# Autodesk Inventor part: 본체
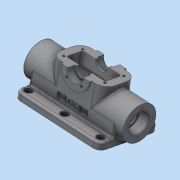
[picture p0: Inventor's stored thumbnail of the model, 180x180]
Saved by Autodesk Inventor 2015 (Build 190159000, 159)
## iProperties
Created: 2024-06
Part Number: 본체
Material: 알루미늄 6061
Document SubType Name: Modeling
Designer: Administrator
Density: 2.7 g/cm^3
Appearance: 기본값
Mass: 551.049 g
Surface Area: 614.928 cm^2
Volume: 204.092 cm^3
Author: Administrator
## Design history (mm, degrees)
sketch "스케치10"
  geometry: L1 (24, -29.5)-(-24, -29.5); L2 (-24, -29.5)-(-24, 29.5); L3 (-24, 29.5)-(24, 29.5); L4 (24, 29.5)-(24, -29.5); L5 (24, -29.5)-(-24, 29.5); L6 (-24, -29.5)-(24, 29.5); 1 further point
  constraints: 12 end point, 2 midpoint, 2 parallel, 1 horizontal, 1 perpendicular
  dimensions: "d38" = 48 distance of L2.end L3.end; "d39" = 59 distance of L3.end L1.start
extrude "돌출7" new body sketch "스케치10" stored distance "d40" = 84; taper "d41" = 0 deg
fillet "모깎기1" dims "d42" = 15
sketch "스케치11"
  geometry: L1 (18, 0)-(0, 0) reference; L2 (33, 15)-(33, 69) reference; L3 (0, 84)-(18, 84) reference; L4 (-15, 69)-(-15, 15) reference; L5 (53, -24)-(-35, -24); L6 (-35, -24)-(-35, 108); L7 (-35, 108)-(53, 108); L8 (53, 108)-(53, -24); L9 (53, -24)-(-35, 108); L10 (-35, -24)-(53, 108); A1 r 15 centre (0, 15) between (-15, 15) and (0, 0) reference; A2 r 15 centre (18, 15) between (18, 0) and (33, 15) reference; A3 r 15 centre (18, 69) between (33, 69) and (18, 84) reference; A4 r 15 centre (0, 69) between (0, 84) and (-15, 69) reference; 1 further point
  constraints: 12 end point, 2 midpoint, 2 parallel, 1 horizontal, 1 perpendicular
  dimensions: "d43" = 88 distance of L5.start L5.end; "d44" = 132 distance of L5.end L6.end
extrude "돌출8" join sketch "스케치11" distance "d45" = 10; taper "d46" = 0 deg
sketch "스케치12"
  geometry: L1 (44, -29.5)-(-44, -29.5) reference; C1 r 24 at (0, -1.5); 1 further point
  constraints: 1 centre point, 1 vertical alignment
  dimensions: "d47" = 48 diameter of C1; "d48" = 28 distance from line of L1 C1.centre
extrude "돌출9" join sketch "스케치12" stored distance "d49" = 154; taper "d50" = 0 deg
sketch "스케치13"
  geometry: L1 (24, -1.5)-(24, -19.5) reference; L2 (-24, -19.5)-(-24, -1.5) reference; L3 (-15.875, -19.5)-(-24, -19.5) reference; L4 (24, -19.5)-(15.875, -19.5) reference; L5 (-24, -1.5)-(-24, -19.5); L6 (15.875, -19.5)-(24, -19.5); L7 (24, -1.5)-(24, -19.5); L8 (-15.875, -19.5)-(-24, -19.5); 1 further point
  constraints: 8 end point, 2 collinear, 2 perpendicular, 2 other
extrude "돌출10" join sketch "스케치13" stored distance "d51" = 132; taper "d52" = 0 deg
sketch "스케치14"
  geometry: L1 (22.5, 77)-(-25.5, 77) reference; L2 (-25.5, -77)-(22.5, -77) reference; L3 (-1.5, 77)-(-1.5, -77); L4 (-29.5, -66)-(-29.5, 66) reference; L5 (12.5, 77)-(12.5, 62); L6 (12.5, 62)-(9.5, 62); L7 (9.5, 62)-(9.5, 60); L8 (9.5, 60)-(16.5, 60); L9 (16.5, 60)-(16.5, -60); L10 (16.5, -60)-(9.5, -60); L11 (9.5, -60)-(9.5, -62); L12 (9.5, -62)-(12.5, -62); L13 (12.5, -62)-(12.5, -77); L14 (22.5, -77)-(22.5, -42) reference; 1 further point
  constraints: 20 end point, 8 perpendicular, 5 point on line, 2 midpoint, 1 collinear, 1 vertical
  dimensions: "d53" = 28 distance between parallel lines of L4 L3; "d54" = 15 distance of L5.start L5.end; "d55" = 15 distance of L12.end L13.end; "d56" = 120 distance of L8.end L9.end; "d57" = 28 diameter of L5 L3; "d58" = 22 diameter of L7 L3; "d59" = 36 diameter of L9 L3
revolve "회전2" sketch "스케치14" stored, may be unused: angle "d60" = 90 deg
sketch "스케치15"
  geometry: L1 (26, 6)-(62, 6); L2 (62, 6)-(62, 126); L3 (62, 126)-(26, 126); L4 (26, 126)-(26, 6); L5 (26, 6)-(62, 126); L6 (62, 6)-(26, 126); 1 further point
  constraints: 12 end point, 2 midpoint, 2 parallel, 1 horizontal, 1 perpendicular
  dimensions: "d61" = 36 distance of L2.end L3.end; "d62" = 120 distance of L1.end L2.end
extrude "돌출11" cut sketch "스케치15" stored distance "d63" = 132; taper "d64" = 0 deg
fillet "모깎기2" dims "d65" = 3
sketch "스케치16"
  geometry: L1 (54, 0)-(0, 0) reference; L2 (5, 0)-(49, 0); A1 r 22 centre (27, 0) between (5, 0) and (49, 0); 2 further points
  constraints: 2 end point, 2 point on circle, 2 point on line, 1 centre point, 1 coincident, 1 midpoint, 1 vertical alignment
  dimensions: "d66" = 44 diameter of A1
extrude "돌출12" join sketch "스케치16" distance "d67" = 3; taper "d68" = 0 deg
sketch "스케치17"
  geometry: L1 (21, -72)-(-3, -72); L2 (-3, -72)-(-3, -12); L3 (-3, -12)-(21, -12); L4 (21, -12)-(21, -72); L5 (21, -72)-(-3, -12); L6 (-3, -72)-(21, -12); 1 further point
  constraints: 12 end point, 2 midpoint, 2 parallel, 1 horizontal, 1 perpendicular
  dimensions: "d69" = 24 distance of L2.end L3.end; "d70" = 60 distance of L3.end L1.start
extrude "돌출13" cut sketch "스케치17" stored distance "d71" = 3; taper "d72" = 0 deg
sketch "스케치18"
  geometry: L1 (-22, 0)-(22, 0) reference; L2 (12, 0)-(-12, 0); A1 r 22 centre (0, 0) between (-22, 0) and (22, 0) reference; A2 r 12 centre (0, 0) between (-12, 0) and (12, 0); 1 further point
  constraints: 2 end point, 2 point on circle, 2 point on line, 1 centre point, 1 coincident
  dimensions: "d73" = 24 diameter of A2
extrude "돌출14" cut sketch "스케치18" distance "d74" = 10; taper "d75" = 0 deg
sketch "스케치19"
  geometry: L1 (-12, 0)-(12, 0) reference; L2 (10, 0)-(-10, 0); A1 r 12 centre (0, 0) between (-12, 0) and (12, 0) reference; A2 r 10 centre (0, 0) between (-10, 0) and (10, 0); 1 further point
  constraints: 2 end point, 2 point on circle, 2 point on line, 1 centre point, 1 coincident
  dimensions: "d76" = 20 diameter of A2
extrude "돌출15" cut sketch "스케치19" stored distance "d77" = 10; taper "d78" = 0 deg
fillet "모깎기3" dims "d79" = 0.3
sketch "스케치20"
  geometry: C1 r 14 at (0, 0) reference; 2 further points
  constraints: 1 vertical alignment
  dimensions: "d80" = 18 distance of point (0, 18) C1.centre
hole "구멍1" sketch "스케치20" at (0, 18) diameter "d81" = 3.242; stored, may be unused: countersink angle "d85" = 90 deg, drill point angle "d87" = 118 deg; dims "d82" = 8, "d83" = 24, "d84" = 10, "d86" = 10
sketch "스케치21"
  geometry: 5 further points
  constraints: 2 horizontal alignment, 2 vertical alignment
  dimensions: "d91" = 28 distance of point (23, 74) point (-5, 74); "d92" = 64 distance of point (-5, 10) point (-5, 74); "d93" = 32 vertical distance of point (9, 42) point (-5, 74); "d94" = 14 horizontal distance of point (9, 42) point (-5, 74)
hole "구멍2" sketch "스케치21" at (-5, 74), (23, 74), (-5, 10), (23, 10) diameter "d95" = 3.242; stored, may be unused: countersink angle "d99" = 90 deg, drill point angle "d101" = 118 deg; dims "d96" = 8, "d97" = 24, "d98" = 10, "d100" = 10
sketch "스케치22"
  geometry: L1 (0, 0)-(0, -15.059); L2 (0, 0)-(-11.314, -11.314); A1 r 22 centre (0, 0) between (-22, 0) and (22, 0) reference; 2 further points
  constraints: 4 end point, 1 coincident, 1 vertical
  dimensions: "d102" = 45 deg angle of L2 L1; "d103" = 16 distance of L1.start L2.end
hole "구멍3" sketch "스케치22" at (-11.314, -11.314) diameter "d104" = 3.242; stored, may be unused: countersink angle "d108" = 90 deg, drill point angle "d110" = 118 deg; dims "d105" = 8, "d106" = 24, "d107" = 10, "d109" = 10
sketch "스케치23"
  geometry: L1 (0, -10)-(132, -10) reference; L2 (123, 18)-(9, 18) reference; 3 further points
  constraints: 1 midpoint, 1 vertical alignment, 1 other
  dimensions: "d111" = 20 distance from line of L1 point (66, 10)
feature "엠보싱1" sketch "스케치23" dims "d112" = 0.5, "d113" = 0
chamfer "모따기1" distance "d114" = 1; stored, may be unused: second distance "d115" = 2, angle "d116" = 45 deg
fillet "모깎기4" dims "d117" = 3
sketch "스케치24"
  geometry: 4 further points
  constraints: 2 vertical alignment, 1 horizontal alignment
  dimensions: "d118" = 34 distance of point (9, -42) point (-25, -42); "d119" = 56 distance of point (-25, -42) point (-25, 14); "d120" = 112 distance of point (-25, -98) point (-25, 14)
hole "구멍4" sketch "스케치24" at (-25, 14), (-25, -42), (-25, -98) diameter "d121" = 6.6; stored, may be unused: countersink angle "d125" = 90 deg, drill point angle "d127" = 0 deg; dims "d122" = 8, "d123" = 11, "d124" = 6.6, "d126" = 10
fillet "모깎기5" dims "d128" = 10
fillet "모깎기6" dims "d129" = 3
fillet "모깎기7" dims "d130" = 3
fillet "모깎기8" dims "d131" = 3
fillet "모깎기9" dims "d132" = 3
chamfer "모따기2" distance "d133" = 1; stored, may be unused: second distance "d134" = 2, angle "d135" = 45 deg
node "솔리드2"
mirror "대칭2"
mirror "대칭3"
pattern_circular "원형 패턴1" dims angle "d89" = 360 deg
mirror "대칭4"
mirror "대칭5"
mirror "대칭6"
mirror "대칭7"
